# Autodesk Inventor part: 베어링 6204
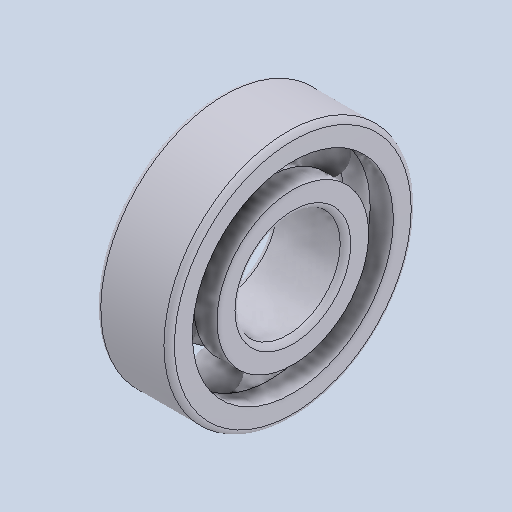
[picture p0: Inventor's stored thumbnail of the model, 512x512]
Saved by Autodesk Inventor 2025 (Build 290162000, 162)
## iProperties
Created: 2024-08
Part Number: 베어링 6204
Material: 강철, 연강
Description: 깊은 그루브 볼 베어링
Document SubType Name: Modeling
Designer: Administrator
Density: 7.86 g/cm^3
Appearance: 기본값
Author: jhkim
Sending System: Autodesk Inventor 2025
Preprocessor: ST-DEVELOPER v20
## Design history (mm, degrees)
feature "Solid1"
feature "Solid1:1"
feature "Solid1:2"
feature "Solid1:3"
feature "Solid1:4"
feature "Solid1:5"
feature "Solid1:6"
feature "Solid1:7"
feature "Solid1:8"
node "솔리드1"
node "솔리드2"
node "솔리드3"
node "솔리드4"
node "솔리드5"
node "솔리드6"
node "솔리드7"
node "솔리드8"
node "솔리드9"
